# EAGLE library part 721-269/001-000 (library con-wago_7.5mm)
Serie 721, Stiftleiste (für Leiterplatten) Einlötstift gerade 1,2x1,2 mm / Series 721, Male header (for PCBs) Straight solder pin 1.2 x 1.2 mm Polzahl / Pole No.: 9 Rastermaß / Pitch: 7.5 mm Bemessungsspannung / Rated Voltage: 630 V Nennstrom / Nominal Current: 16 A Lötstiftlänge: / Solder Pin Length: 5 mm Farbe / Color: lichtgrau / light gray Stand: 01.01.2012. Die jeweils aktuellen Daten zu diesem Artikel finden Sie in unserem Produktkatalog, den Sie unter www.wago.com einsehen können. As of: 01/01/2012. Please find the newest data for this article in our product catalogue, which can be viewed under www.wago.com.
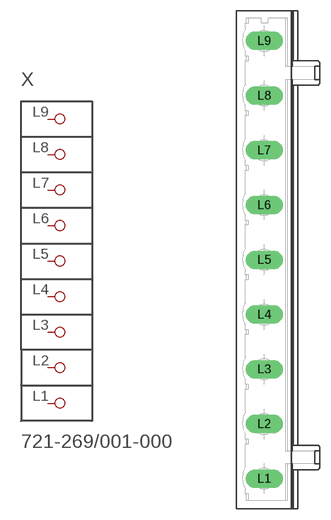
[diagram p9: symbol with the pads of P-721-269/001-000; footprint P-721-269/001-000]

Designator prefix X

## 721-269/001-000  [P-721-269/001-000]
L1  P1
L2  P2
L3  P3
L4  P4
L5  P5
L6  P6
L7  P7
L8  P8
L9  P9

## Footprint P-721-269/001-000 (pad centres in mm)
drill 1.7 long: L1 -1.9,-30; L2 -1.9,-22.5; L3 -1.9,-15; L4 -1.9,-7.5; L5 -1.9,0; L6 -1.9,7.5; L7 -1.9,15; L8 -1.9,22.5; L9 -1.9,30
